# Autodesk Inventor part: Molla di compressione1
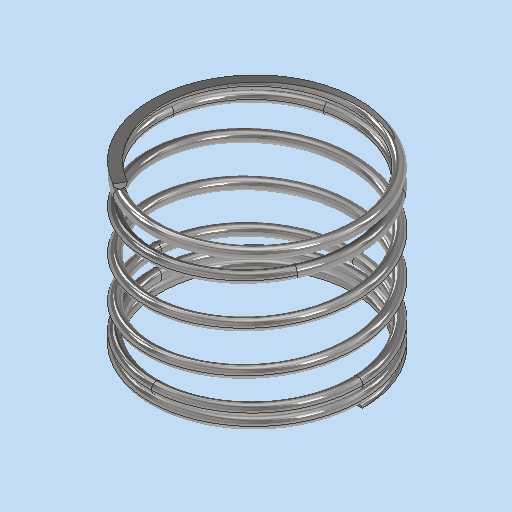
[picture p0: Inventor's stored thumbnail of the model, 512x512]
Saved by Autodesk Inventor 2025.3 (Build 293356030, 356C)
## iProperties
CustomPartVersion: 1
Created: 2026-05
Part Number: Molla di compressione1
Material: Steel
Document SubType Name: Modeling
Designer: R5800u
Density: 2.18 g/cm^3
Appearance: Acciaio - Lucido
Author: R5800u
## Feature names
1. Main Coil Feature(R)
2. Inizio spira transizione 1 (destra)
3. Coil  Start Transition 2(R)
4. Coil  Start Transition 3(R)
5. Coil  Start Transition 4(R)
6. Inizio spira estremità (destra)
7. Inizio lavorazione taglio (destra) [Extrusion]
8. Fine spira transizione 1 (destra)
9. Fine spira transizione 2 (destra)
10. Fine spira transizione 3 (destra)
11. Fine spira transizione 4 (destra)
12. Spira di estremità (destra)
13. Fine lavorazione taglio (destra) [Extrusion]
14. Lavorazione taglio estremità piane 1 (destra) [Extrusion]
15. Plain Ends Cut  2(R) [Extrusion]
16. Main Coil Feature(L)
17. Inizio spira transizione 1 (sinistra)
18. Inizio spira transizione 2 (sinistra)
19. Inizio spira transizione 3 (sinistra)
20. Inizio spira transizione 4 (sinistra)
21. Inizio spira estremità (sinistra)
22. Inizio lavorazione taglio (sinistra) [Extrusion]
23. Fine spira transizione 1 (sinistra)
24. Fine spira transizione 2 (sinistra)
25. Fine spira transizione 3 (sinistra)
26. Fine spira transizione 4 (sinistra)
27. Spira di estremità (sinistra)
28. Fine lavorazione taglio (sinistra) [Extrusion]
29. Cut Plain Ends Cut 1(L) [Extrusion]
30. Cut Plain Ends Cut 2(L) [Extrusion]
## Parameters: d0 = 0.125 mm, da_d = 0.5 mm, da_D2 = 9 mm, da_n = 41.6858 mm, da_ti = 1.94331 mm, da_nz1 = 15 mm, spiral_Angle = 0.65021 mm, d2 = 1.94331 mm, d4 = 24.1858 mm, d5 = 0, d6 = 90 deg, d7 = 90 deg, d8 = 0, d9 = 0, d12 = 1.28093 mm, d13 = -1.66651 mm, d14 = 0.5 mm, d15 = 0, d16 = 1.58248 mm, d18 = 2.5 mm, d19 = 0, d20 = 90 deg, d21 = 90 deg, d22 = 0, d23 = 0, d24 = 1.22166 mm, d26 = 2.5 mm, d27 = 0, d28 = 90 deg, d29 = 90 deg, d30 = 0, d31 = 0, d32 = 0.86083 mm, d34 = 2.5 mm, d35 = 0, d36 = 90 deg, d37 = 90 deg, d38 = 0, d39 = 0, d40 = 0.5 mm, d42 = 2.5 mm, d43 = 0, d44 = 90 deg, d45 = 90 deg, d46 = 0, d47 = 0, d48 = 1.58248 mm, d50 = 1.875 mm, d51 = 0, d52 = 90 deg, d53 = 90 deg, d54 = 0, d55 = 0, d56 = 1.22166 mm, d58 = 1.875 mm, d59 = 0, d60 = 90 deg, d61 = 90 deg, d62 = 0, d63 = 0, d64 = 0.86083 mm, d66 = 1.875 mm, d67 = 0, d68 = 90 deg, d69 = 90 deg, d70 = 0, d71 = 0, d72 = 0.5 mm, d74 = 1.875 mm, d75 = 0, d76 = 90 deg, d77 = 90 deg, d78 = 0, d79 = 0, End_Pitch = 0.50106 mm, d82 = 15 mm, d83 = 0, d84 = 90 deg, d85 = 90 deg, d86 = 0, d87 = 0, d88 = 0.50106 mm, d91 = 0, d92 = 90 deg, d93 = 90 deg, d94 = 0, d95 = 0, d97 = 0.50106 mm, d98 = 0, d100 = 0.50106 mm, d101 = 0, d102 = 0, d103 = 0, d104 = 0, d105 = 0, d106 = 0, d108 = 0, d112 = 0, d113 = 0, d114 = 0, const_zero = 0, Not_rightdir = 0, d121 = 0.12632 mm, d131 = 0, d132 = 0, d133 = 0, d134 = 0, d135 = 0.125 mm, d137 = 1.94331 mm, d139 = 24.1858 mm, d140 = 0, d141 = 90 deg, d142 = 90 deg, d143 = 0, d144 = 0, d145 = 1.28093 mm, d146 = -1.66651 mm, d147 = 0.12632 mm, d148 = 0.00106 mm, d149 = 0.5 mm, d150 = 0, d151 = 0, d152 = 1.58248 mm, d154 = 2.5 mm, d155 = 0, d156 = 90 deg, d157 = 90 deg, d158 = 0, d159 = 0, d160 = 1.22166 mm, d162 = 2.5 mm, d163 = 0, d164 = 90 deg, d165 = 90 deg, d166 = 0, d167 = 0, d168 = 0.86083 mm, d170 = 2.5 mm, d171 = 0, d172 = 90 deg, d173 = 90 deg, d174 = 0, d175 = 0, d176 = 0.5 mm, d178 = 2.5 mm, d179 = 0, d180 = 90 deg, d181 = 90 deg, d182 = 0, d183 = 0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
